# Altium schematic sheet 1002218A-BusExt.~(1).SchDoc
size B; Organization: Monterey Bay Aquarium Research Institute; Address1: 7700 Sandholdt Rd; Address2: Moss Landing, CA 95039-9644; CompanyName: MBARI
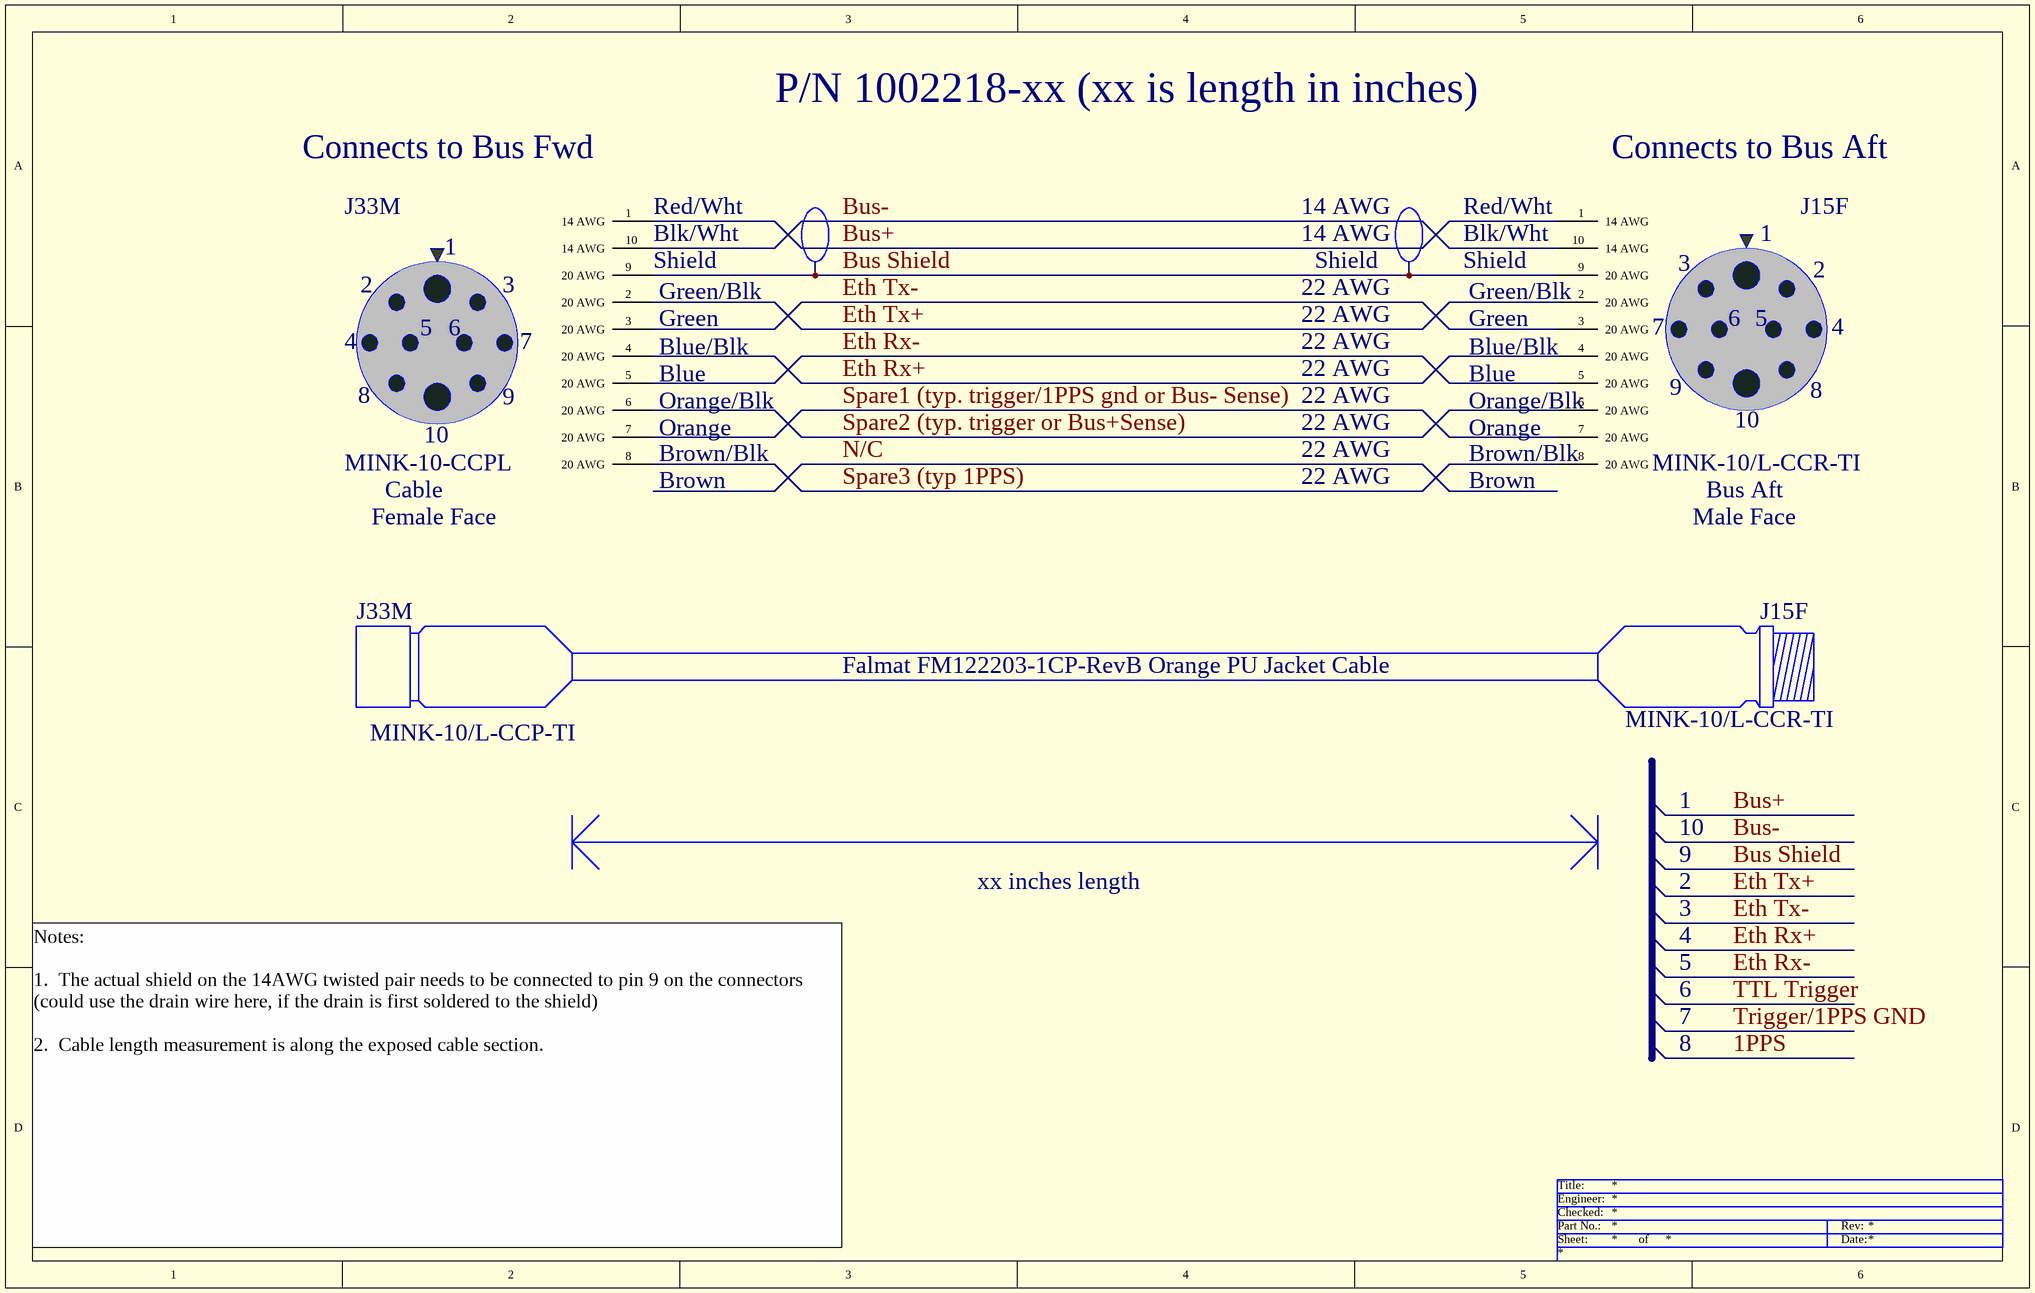
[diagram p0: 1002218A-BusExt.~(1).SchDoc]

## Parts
(Parts that share a designator on the sheet are numbered #1, #2 ... from top to bottom, then left to right.)
J15F#1  MINK-10/L-CCR-TI  DescSheet: Bus Aft  View: Male Face
J15F#2  MINK-10/L-CCR-TI
J33M#1  MINK-10-CCPL  DescSheet: Cable  View: Female Face
J33M#2  MINK-10/L-CCP-TI

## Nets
Bus Shield: J15F#1.9(20_AWG) J33M#1.9(20_AWG)
Bus+: J15F#1.1(14_AWG) J33M#1.1(14_AWG)
Bus-: J15F#1.10(14_AWG) J33M#1.10(14_AWG)
Eth Rx+: J15F#1.4(20_AWG) J33M#1.4(20_AWG)
Eth Rx-: J15F#1.5(20_AWG) J33M#1.5(20_AWG)
Eth Tx+: J15F#1.2(20_AWG) J33M#1.2(20_AWG)
Eth Tx-: J15F#1.3(20_AWG) J33M#1.3(20_AWG)
Spare1 (typ. trigger/1PPS gnd or Bus- Sense): J15F#1.7(20_AWG) J33M#1.7(20_AWG)
Spare2 (typ. trigger or Bus+Sense): J15F#1.6(20_AWG) J33M#1.6(20_AWG)
Spare3 (typ 1PPS): J15F#1.8(20_AWG) J33M#1.8(20_AWG)

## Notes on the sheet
- Connects to Bus Fwd
- P/N 1002218-xx (xx is length in inches)
- Connects to Bus Aft
- (near J33M#1) Red/Wht
- 14 AWG
- (near J15F#1) Red/Wht
- (near J33M#1) Blk/Wht
- (near J33M#1) Shield
- (near J33M#1) Green/Blk
- 22 AWG
- Shield
- (near J15F#1) Blk/Wht
- (near J15F#1) Green/Blk
- (near J33M#1) Green
- (near J33M#1) Blue/Blk
- Green
- (near J15F#1) Blue/Blk
- (near J33M#1) Blue
- (near J33M#1) Orange
- (near J33M#1) Orange/Blk
- Blue
- Orange
- (near J15F#1) Orange/Blk
- (near J33M#1) Brown/Blk
- (near J33M#1) Brown
- (near J15F#1) Brown/Blk
- Brown
- Falmat FM122203-1CP-RevB Orange PU Jacket Cable
- 1
- 10
- xx inches length
- 2
- 9
- 3
- 4
- 5
- 6
- 7
- 8
- Notes:
  1.  The actual shield on the 14AWG twisted pair needs to be connected to pin 9 on the connectors (could use the drain wire here, if the drain is first soldered to the shield)
  2.  Cable length measurement is along the exposed cable section.

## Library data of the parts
J15F#1 = SEACON-MINK-10-BCR-PINS: Seacon MINK-10/L-CCR Connector
J15F#2 = CONN-MIN-CCR-LARGE: Seacon MIN Connector CCR
J33M#1 = SEACON-MINK-10-CCP-SOC: Seacon MINK-10/L-CCP Connector
J33M#2 = CONN-MIN-CCP-LARGE: Seacon MINK Connector CCP; DescSheet: Bus Fwd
